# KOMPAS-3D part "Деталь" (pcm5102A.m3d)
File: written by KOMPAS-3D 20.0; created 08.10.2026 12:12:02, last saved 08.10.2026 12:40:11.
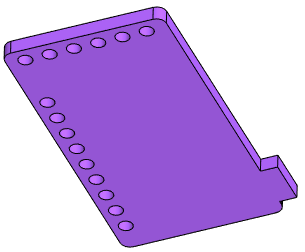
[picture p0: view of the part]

Document properties: Полное имя файла: D:\RicWork\Project-EPS32\box_compas\pcm5102A.m3d

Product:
- Part/product: Деталь
    Масса: 0.00613645

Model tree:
1. Эскиз:1
2. Элемент выдавливания:1
     Расстояние 1 = 1.5
3. Скругление:1  (with: Элемент выдавливания:1)
     Радиус = 1
4. Эскиз:2  (with: Элемент выдавливания:1)
5. Элемент выдавливания:2
6. Массив по сетке:1  (with: Элемент выдавливания:2, Эскиз:2)  (9 pattern instances)
     Шаг 1 = 10; Угол раствора = -90; Шаг 2 = 2.54
7. Эскиз:3  (with: Элемент выдавливания:1)
8. Элемент выдавливания:3
9. Массив по сетке:2  (with: Элемент выдавливания:3, Эскиз:3, Скругление:1)  (6 pattern instances)
     Шаг 1 = 2.54; Угол раствора = 90

Referenced files in D:\RicWork\Project-EPS32\box_compas\: pcm5102A.png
